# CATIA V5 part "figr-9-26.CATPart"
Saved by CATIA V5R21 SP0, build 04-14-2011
Part number: Part1
Bounding box of the stored display mesh (mm): x -75 to 75, y -50 to 50, z 0 to 40
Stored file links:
  D:\CATIA V5R21 E-RESOURCES\CATIA-V5R21\catia-v5r21-prt\c09-catia-v5r20-prt\c09-catia-v5r21-figr-9-26.CATPart
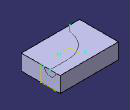
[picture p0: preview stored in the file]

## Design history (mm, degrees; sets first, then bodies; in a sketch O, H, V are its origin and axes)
Body1 (main body)
  Sketch1 on xy-plane, origin (0, 0, 0), H (1, 0, 0), V (0, 1, 0)
    line L1 (-75, 50) -> (75, 50)
    line L2 (75, 50) -> (75, -50)
    line L3 (75, -50) -> (-75, -50)
    line L4 (-75, -50) -> (-75, 50)
    axis line L5 (75, -50) -> (-75, 50)
    length L2 = 100
    length L3 = 150
    horizontal: L1 H, L3 H
    vertical: L2 V, L4 V
    midpoint: O L5
  Pad1: profile Sketch1, direction (0, 0, 1), length 40
  Sketch2 on face of Pad1, origin (75, 0, 0), H (0, 1, 0), V (0, 0, 1)
    arc A1 centre (24.1478, 40) radius 14.6047 from (9.543, 40) to (38.7525, 40) ccw
    point P1 (24.1478, 40)
    reference projected point E1 (24.1478, 40) from vertex of Sketch3
    line L1 (9.543, 40) -> (38.7525, 40)
    coincidence: P1 E1
    horizontal: L1 H
  Sketch3 on face of Pad1, origin (0, 0, 40), H (1, 0, 0), V (0, 1, 0)
    point P1 (75, 24.1478)
    line L1 (75, 24.1478) -> (28.6577, 24.1478)
    arc A1 centre (28.6577, -39.2062) radius 63.354 from (28.6577, 24.1478) to (-33.8383, -28.8149) ccw
    arc A2 centre (-62.192, -24.1005) radius 28.7429 from (-33.8383, -28.8149) to (-49.7271, -50) cw
    point P6 (-49.7271, -50)
    reference projected line E1 (75, -50) -> (75, 50) from edge [face of Pad1 | face of Pad1]
    reference projected line E2 (-75, -50) -> (75, -50) from edge [face of Pad1 | face of Pad1]
    horizontal: L1 H
    tangency: A1 L1, A2 A1
    coincidence: P1 E1, P6 E2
